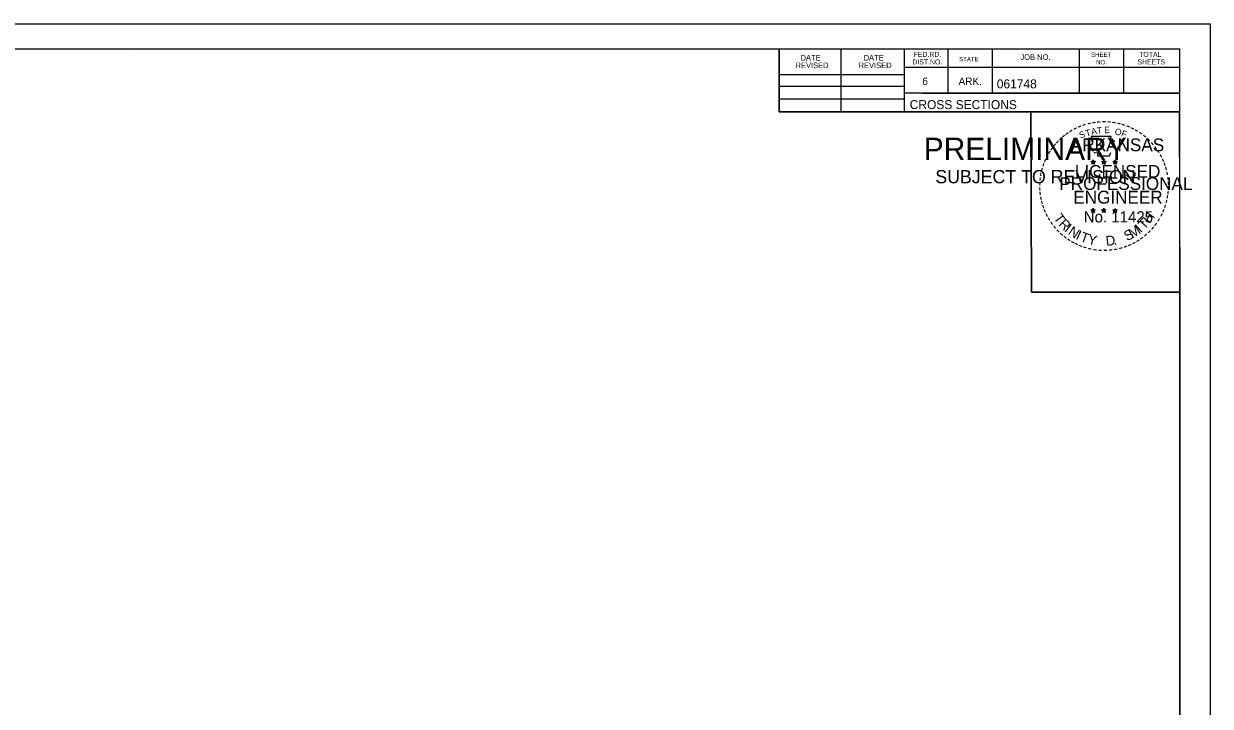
# Model space of a CAD drawing. Extents: x 961436 to 1372525, y 380079 to 2027791.
# Drawn here: x 1370167.9 to 1370353.4, y 380642.4 to 380749.1 of the extents above; entities that cross this region are included whole.
import ezdxf

# ---------------------------------------------------------------- set-up
doc = ezdxf.new("R2010")
doc.units = 0
doc.layers.add('R_No Plot', color=7, linetype='Continuous')

msp = doc.modelspace()

# ---------------------------------------------------------------- linework, layer by layer
at = {"layer": 'R_No Plot'}
for p, q in [((1370020.1, 380749.09), (1370353.44, 380749.09)), ((1370032.5, 380745.19), (1370348.68, 380745.19)), ((1370185.02, 380744.93), (1370185.02, 380744.93)), ((1370185.02, 380744.93), (1370185.02, 380744.93)), ((1370286.04, 380735.31), (1370286.04, 380745.19)), ((1370295.72, 380735.31), (1370295.72, 380745.19)), ((1370305.58, 380745.19), (1370305.58, 380735.31)), ((1370312.42, 380745.19), (1370312.42, 380738.25)), ((1370319.36, 380745.19), (1370319.36, 380738.25)), ((1370332.94, 380745.19), (1370332.94, 380738.25)), ((1370339.88, 380745.19), (1370339.88, 380738.25)), ((1370348.68, 380539.73), (1370348.68, 380745.19)), ((1370348.68, 380742.25), (1370305.58, 380742.25)), ((1370348.68, 380742.27), (1370348.68, 380742.27)), ((1370286.04, 380741.17), (1370305.58, 380741.17)), ((1370286.04, 380739.31), (1370305.58, 380739.31)), ((1370348.68, 380738.25), (1370305.58, 380738.25)), ((1370308.54, 380738.25), (1370348.68, 380738.25)), ((1370286.04, 380737.37), (1370305.58, 380737.37)), ((1370348.68, 380735.31), (1370286.04, 380735.31)), ((1370334.77, 380727.57), (1370335.12, 380727.46)), ((1370334.77, 380727.57), (1370335.02, 380727.53)), ((1370334.77, 380727.57), (1370335.01, 380727.45)), ((1370334.9, 380727.16), (1370335.12, 380727.46)), ((1370334.9, 380727.16), (1370335.03, 380727.41)), ((1370334.9, 380727.16), (1370335.12, 380727.38)), ((1370335.12, 380727.82), (1370335.08, 380727.57)), ((1370335.12, 380727.46), (1370335.12, 380727.82)), ((1370335.12, 380727.82), (1370335.17, 380727.57)), ((1370335.47, 380727.57), (1370335.12, 380727.46)), ((1370335.33, 380727.16), (1370335.12, 380727.46)), ((1370335.33, 380727.16), (1370335.12, 380727.38)), ((1370335.47, 380727.57), (1370335.18, 380727.52)), ((1370335.33, 380727.16), (1370335.19, 380727.45)), ((1370335.47, 380727.57), (1370335.26, 380727.47)), ((1370336.44, 380727.57), (1370336.79, 380727.46)), ((1370336.44, 380727.57), (1370336.69, 380727.53)), ((1370336.44, 380727.57), (1370336.68, 380727.45)), ((1370336.57, 380727.16), (1370336.79, 380727.46)), ((1370336.57, 380727.16), (1370336.7, 380727.41)), ((1370336.57, 380727.16), (1370336.79, 380727.38)), ((1370336.79, 380727.82), (1370336.75, 380727.57)), ((1370336.79, 380727.46), (1370336.79, 380727.82)), ((1370336.79, 380727.82), (1370336.84, 380727.57)), ((1370337.14, 380727.57), (1370336.79, 380727.46)), ((1370337, 380727.16), (1370336.79, 380727.46)), ((1370337, 380727.16), (1370336.79, 380727.38)), ((1370337.14, 380727.57), (1370336.85, 380727.52)), ((1370337, 380727.16), (1370336.86, 380727.45)), ((1370337.14, 380727.57), (1370336.93, 380727.47)), ((1370338.2, 380727.56), (1370338.55, 380727.45)), ((1370338.2, 380727.56), (1370338.46, 380727.51)), ((1370338.2, 380727.56), (1370338.44, 380727.44)), ((1370338.34, 380727.15), (1370338.55, 380727.45)), ((1370338.34, 380727.15), (1370338.46, 380727.39)), ((1370338.34, 380727.15), (1370338.55, 380727.37)), ((1370338.55, 380727.81), (1370338.51, 380727.56)), ((1370338.55, 380727.45), (1370338.55, 380727.81)), ((1370338.55, 380727.81), (1370338.6, 380727.56)), ((1370338.9, 380727.56), (1370338.55, 380727.45)), ((1370338.77, 380727.15), (1370338.55, 380727.45)), ((1370338.77, 380727.15), (1370338.55, 380727.36)), ((1370338.9, 380727.56), (1370338.61, 380727.51)), ((1370338.77, 380727.15), (1370338.63, 380727.44)), ((1370338.9, 380727.56), (1370338.7, 380727.46)), ((1370334.77, 380720), (1370335.11, 380719.89)), ((1370334.77, 380720), (1370335.02, 380719.95)), ((1370334.77, 380720), (1370335, 380719.88)), ((1370334.9, 380719.59), (1370335.11, 380719.89)), ((1370334.9, 380719.59), (1370335.02, 380719.83)), ((1370334.9, 380719.59), (1370335.11, 380719.81)), ((1370335.11, 380720.25), (1370335.07, 380720)), ((1370335.11, 380719.89), (1370335.11, 380720.25)), ((1370335.11, 380720.25), (1370335.16, 380720)), ((1370335.46, 380720), (1370335.11, 380719.89)), ((1370335.33, 380719.59), (1370335.11, 380719.89)), ((1370335.33, 380719.59), (1370335.11, 380719.8)), ((1370335.46, 380720), (1370335.18, 380719.95)), ((1370335.33, 380719.59), (1370335.19, 380719.88)), ((1370335.46, 380720), (1370335.26, 380719.9)), ((1370336.43, 380720), (1370336.78, 380719.89)), ((1370336.43, 380720), (1370336.69, 380719.95)), ((1370336.43, 380720), (1370336.67, 380719.88)), ((1370336.57, 380719.59), (1370336.78, 380719.89)), ((1370336.57, 380719.59), (1370336.69, 380719.83)), ((1370336.57, 380719.59), (1370336.78, 380719.81)), ((1370336.78, 380720.25), (1370336.74, 380720)), ((1370336.78, 380719.89), (1370336.78, 380720.25)), ((1370336.78, 380720.25), (1370336.83, 380720)), ((1370337.13, 380720), (1370336.78, 380719.89)), ((1370337, 380719.59), (1370336.78, 380719.89)), ((1370337, 380719.59), (1370336.78, 380719.8)), ((1370337.13, 380720), (1370336.84, 380719.95)), ((1370337, 380719.59), (1370336.86, 380719.88)), ((1370337.13, 380720), (1370336.93, 380719.9)), ((1370338.2, 380719.99), (1370338.55, 380719.88)), ((1370338.2, 380719.99), (1370338.45, 380719.94)), ((1370338.2, 380719.99), (1370338.44, 380719.87)), ((1370338.33, 380719.58), (1370338.55, 380719.88)), ((1370338.33, 380719.58), (1370338.46, 380719.82)), ((1370338.33, 380719.58), (1370338.55, 380719.8)), ((1370338.55, 380720.24), (1370338.51, 380719.99)), ((1370338.55, 380719.88), (1370338.55, 380720.24)), ((1370338.55, 380720.24), (1370338.6, 380719.99)), ((1370338.9, 380719.99), (1370338.55, 380719.88)), ((1370338.76, 380719.58), (1370338.55, 380719.88)), ((1370338.76, 380719.58), (1370338.55, 380719.79)), ((1370338.9, 380719.99), (1370338.61, 380719.94)), ((1370338.76, 380719.58), (1370338.63, 380719.87)), ((1370338.9, 380719.99), (1370338.69, 380719.89)), ((1370324.72, 380712.86), (1370324.72, 380712.86))]:
    msp.add_line(p, q, dxfattribs=at)
for points in [[(1370020.1, 380749.09), (1370353.44, 380749.09), (1370353.44, 380535.75), (1370020.1, 380535.75)], [(1370266.42, 380745.19), (1370286.04, 380745.19), (1370286.04, 380735.31), (1370302.16, 380735.31), (1370325.36, 380735.31), (1370325.48, 380707.16), (1370348.68, 380707.16), (1370348.68, 380539.73), (1370032.5, 380539.73), (1370032.5, 380745.19)], [(1370325.36, 380735.31), (1370348.56, 380735.31), (1370348.68, 380707.16), (1370325.48, 380707.16)]]:
    msp.add_lwpolyline(points, close=True, dxfattribs=at)
for points in [[(1370334.81, 380731.45), (1370335.08, 380730.62)], [(1370338.32, 380730.53), (1370338.46, 380730.81), (1370337.78, 380730.79), (1370337.93, 380731.45), (1370334.81, 380731.45)], [(1370335.3, 380729.03), (1370335.3, 380728.94), (1370335.87, 380728.92), (1370335.81, 380728.45), (1370337.68, 380728.45), (1370337.88, 380728.98)], [(1370335.12, 380727.82), (1370335.33, 380727.16), (1370334.77, 380727.57), (1370335.47, 380727.57), (1370334.9, 380727.16), (1370335.12, 380727.82)], [(1370336.79, 380727.82), (1370337, 380727.16), (1370336.44, 380727.57), (1370337.14, 380727.57), (1370336.57, 380727.16), (1370336.79, 380727.82)], [(1370338.55, 380727.81), (1370338.77, 380727.15), (1370338.2, 380727.56), (1370338.9, 380727.56), (1370338.34, 380727.15), (1370338.55, 380727.81)], [(1370335.11, 380720.25), (1370335.33, 380719.59), (1370334.77, 380720), (1370335.46, 380720), (1370334.9, 380719.59), (1370335.11, 380720.25)], [(1370336.78, 380720.25), (1370337, 380719.59), (1370336.43, 380720), (1370337.13, 380720), (1370336.57, 380719.59), (1370336.78, 380720.25)], [(1370338.55, 380720.24), (1370338.76, 380719.58), (1370338.2, 380719.99), (1370338.9, 380719.99), (1370338.33, 380719.58), (1370338.55, 380720.24)]]:
    msp.add_lwpolyline(points, dxfattribs=at)
for centre, radius in [((1370335.12, 380727.46), 0.172), ((1370335.12, 380727.46), 0.145), ((1370335.12, 380727.46), 0.116), ((1370335.12, 380727.46), 0.0991), ((1370335.12, 380727.46), 0.0747), ((1370335.12, 380727.46), 0.0495), ((1370335.12, 380727.46), 0.0296), ((1370336.79, 380727.46), 0.172), ((1370336.79, 380727.46), 0.145), ((1370336.79, 380727.46), 0.116), ((1370336.79, 380727.46), 0.0991), ((1370336.79, 380727.46), 0.0747), ((1370336.79, 380727.46), 0.0495), ((1370336.79, 380727.46), 0.0296), ((1370338.55, 380727.45), 0.172), ((1370338.55, 380727.45), 0.145), ((1370338.55, 380727.45), 0.116), ((1370338.55, 380727.45), 0.0991), ((1370338.55, 380727.45), 0.0747), ((1370338.55, 380727.45), 0.0495), ((1370338.55, 380727.45), 0.0296), ((1370335.11, 380719.89), 0.172), ((1370335.11, 380719.89), 0.145), ((1370335.11, 380719.89), 0.116), ((1370335.11, 380719.89), 0.0991), ((1370335.11, 380719.89), 0.0747), ((1370335.11, 380719.89), 0.0495), ((1370335.11, 380719.89), 0.0296), ((1370336.78, 380719.89), 0.172), ((1370336.78, 380719.89), 0.145), ((1370336.78, 380719.89), 0.116), ((1370336.78, 380719.89), 0.0991), ((1370336.78, 380719.89), 0.0747), ((1370336.78, 380719.89), 0.0495), ((1370336.78, 380719.89), 0.0296), ((1370338.55, 380719.88), 0.172), ((1370338.55, 380719.88), 0.145), ((1370338.55, 380719.88), 0.116), ((1370338.55, 380719.88), 0.0991), ((1370338.55, 380719.88), 0.0747), ((1370338.55, 380719.88), 0.0495), ((1370338.55, 380719.88), 0.0296)]:
    msp.add_circle(centre, radius, dxfattribs=at)

# ---------------------------------------------------------------- texts
for s, height, rotation, p in [('DATE', 0.879, 360, (1370289.38, 380743.33)), ('DATE', 0.879, 360, (1370299.24, 380743.33)), ('FED.RD.', 0.782, 360, (1370307.06, 380743.91)), ('STATE', 0.684, 360, (1370314.18, 380743.23)), ('JOB NO.', 0.879, 360, (1370323.76, 380743.43)), ('SHEET', 0.684, 360, (1370334.8, 380743.91)), ('TOTAL', 0.782, 360, (1370342.32, 380743.91)), ('REVISED', 0.879, 360, (1370288.6, 380742.15)), ('REVISED', 0.879, 360, (1370298.46, 380742.15)), ('DIST.NO.', 0.782, 360, (1370306.86, 380742.73)), ('NO.', 0.684, 360, (1370335.58, 380742.73)), ('SHEETS', 0.782, 360, (1370342.04, 380742.73)), ('6', 1.17, 360, (1370308.42, 380739.51)), ('ARK.', 1.172, 360, (1370314.08, 380739.51)), ('061748', 1.4, 360, (1370320.06, 380738.99)), ('CROSS SECTIONS', 1.4, 360, (1370306.45, 380735.75)), ('-', 1.6, 34.0636, (1370331.69, 380731.62)), ('-', 1.6, 28.7918, (1370332.29, 380731.99)), ('-', 1.6, 24.3072, (1370332.92, 380732.31)), ('-', 1.6, 19.1761, (1370333.56, 380732.58)), ('T', 1, 16.4036, (1370334.08, 380731.46)), ('-', 1.6, 13.6301, (1370334.31, 380732.82)), ('A', 1, 11.2132, (1370334.91, 380731.71)), ('-', 1.6, 10.2193, (1370334.99, 380732.98)), ('T', 1, 6.0228, (1370335.75, 380731.87)), ('-', 1.6, 5.8968, (1370335.72, 380733.09)), ('-', 1.6, 0.1862, (1370336.49, 380733.16)), ('E', 1, 0.8323, (1370336.86, 380731.98)), ('-', 1.6, 357.743, (1370337.21, 380733.15)), ('-', 1.6, 352.1617, (1370337.95, 380733.09)), ('O', 1, 350.4515, (1370338.46, 380731.77)), ('-', 1.6, 347.2049, (1370338.67, 380732.98)), ('-', 1.6, 342.3362, (1370339.31, 380732.82)), ('-', 1.6, 337.8551, (1370340.04, 380732.6)), ('-', 1.6, 334.1211, (1370340.67, 380732.33)), ('-', 1.6, 329.6409, (1370341.25, 380732.05)), ('PRELIMINARY', 3.5, 360, (1370308.64, 380727.78)), ('-', 1.6, 48.423, (1370329.76, 380729.95)), ('-', 1.6, 42.9622, (1370330.21, 380730.43)), ('-', 1.6, 38.9507, (1370330.64, 380730.85)), ('-', 1.6, 36.2317, (1370331.12, 380731.22)), ('ARKANSAS', 2, 360, (1370331.66, 380729.16)), ('S', 1, 21.594, (1370333.17, 380731.13)), ('F', 1, 340.0707, (1370339.42, 380731.55)), ('-', 1.6, 325.8627, (1370341.9, 380731.68)), ('-', 1.6, 320.5297, (1370342.51, 380731.26)), ('-', 1.6, 315.5786, (1370343.11, 380730.77)), ('DWB', 0.01, 360, (1370309.38, 380729.63)), ('-', 1.6, 58.0706, (1370328.62, 380728.37)), ('-', 1.6, 54.2325, (1370328.94, 380728.9)), ('-', 1.6, 50.6142, (1370329.36, 380729.47)), ('-', 1.6, 309.8797, (1370343.67, 380730.22)), ('-', 1.6, 306.6522, (1370344.2, 380729.62)), ('-', 1.4, 303.6753, (1370344.69, 380729.05)), ('-', 1.6, 72.3945, (1370327.83, 380726.52)), ('-', 1.6, 67.7743, (1370328.05, 380727.15)), ('-', 1.6, 62.8713, (1370328.31, 380727.76)), ('LICENSED', 2, 360, (1370332.26, 380725.01)), ('DWB', 0.01, 360, (1370335.11, 380727.45)), ('DWB', 0.01, 360, (1370336.78, 380727.45)), ('DWB', 0.01, 360, (1370338.54, 380727.44)), ('-', 1.6, 299.6684, (1370345, 380728.44)), ('-', 1.6, 294.6628, (1370345.33, 380727.83)), ('-', 1.6, 290.5728, (1370345.59, 380727.25)), ('SUBJECT TO REVISION', 2.0751, 360, (1370310.45, 380724.15)), ('-', 1.6, 81.2013, (1370327.5, 380725.09)), ('-', 1.6, 75.461, (1370327.63, 380725.8)), ('PROFESSIONAL', 2, 360, (1370329.84, 380723.11)), ('-', 1.6, 285.1233, (1370345.82, 380726.67)), ('-', 1.6, 280.5493, (1370346.02, 380725.93)), ('-', 1.6, 276.5962, (1370346.18, 380725.16)), ('-', 1.6, 94.1959, (1370327.43, 380722.97)), ('-', 1.6, 89.0622, (1370327.4, 380723.7)), ('-', 1.6, 85.1863, (1370327.42, 380724.4)), ('-', 1.6, 274.3301, (1370346.24, 380724.44)), ('-', 1.6, 269.9407, (1370346.28, 380723.81)), ('-', 1.6, 98.9479, (1370327.5, 380722.31)), ('-', 1.6, 101.7149, (1370327.64, 380721.57)), ('-', 1.6, 105.4578, (1370327.8, 380720.98)), ('ENGINEER', 2, 360, (1370332.02, 380720.98)), ('-', 1.6, 255.7626, (1370346.08, 380721.81)), ('-', 1.6, 260.9953, (1370346.19, 380722.49)), ('-', 1.6, 263.5172, (1370346.26, 380723.14)), ('-', 1.6, 109.0874, (1370328.02, 380720.35)), ('-', 1.6, 114.0643, (1370328.27, 380719.75)), ('T', 1.54, 306.0406, (1370328.87, 380718.72)), ('No. 11425', 1.757, 360, (1370333.65, 380718.03)), ('DWB', 0.01, 360, (1370335.1, 380719.88)), ('DWB', 0.01, 360, (1370336.77, 380719.88)), ('DWB', 0.01, 360, (1370338.54, 380719.87)), ('H', 1.54, 54.6088, (1370343.99, 380717.76)), ('-', 1.6, 247.8887, (1370345.67, 380720.42)), ('-', 1.6, 252.8681, (1370345.89, 380721.09)), ('-', 1.6, 115.7289, (1370328.58, 380719.13)), ('-', 1.6, 120.4471, (1370328.93, 380718.55)), ('-', 1.6, 125.8934, (1370329.34, 380717.99)), ('R', 1.54, 314.005, (1370329.64, 380717.68)), ('I', 1.54, 321.9694, (1370330.54, 380716.74)), ('I', 1.54, 42.1136, (1370342.54, 380716.34)), ('T', 1.54, 46.6444, (1370343.11, 380716.82)), ('-', 1.6, 233.8452, (1370344.61, 380718.39)), ('-', 1.6, 239.0712, (1370345.02, 380719.04)), ('-', 1.6, 244.6197, (1370345.41, 380719.79)), ('-', 1.6, 130.7181, (1370329.8, 380717.43)), ('-', 1.6, 134.2238, (1370330.31, 380716.89)), ('-', 1.6, 138.9338, (1370330.84, 380716.42)), ('-', 1.6, 144.6463, (1370331.4, 380716.02)), ('N', 1.54, 326.5002, (1370331.1, 380716.27)), ('I', 1.54, 335.3603, (1370332.31, 380715.49)), ('T', 1.54, 339.8912, (1370332.97, 380715.16)), ('Y', 1.54, 347.8556, (1370334.19, 380714.71)), ('D', 1.54, 6.3969, (1370337.18, 380714.36)), ('S', 1.54, 26.9312, (1370340.42, 380715.09)), ('M', 1.54, 32.6563, (1370341.26, 380715.49)), ('-', 1.6, 221.0851, (1370343.18, 380716.75)), ('-', 1.6, 225.7653, (1370343.7, 380717.26)), ('-', 1.6, 231.2538, (1370344.18, 380717.82)), ('-', 1.6, 148.0898, (1370331.96, 380715.65)), ('-', 1.6, 151.5704, (1370332.54, 380715.32)), ('-', 1.6, 154.6002, (1370333.06, 380715.08)), ('-', 1.6, 158.5612, (1370333.68, 380714.82)), ('-', 1.6, 162.7983, (1370334.37, 380714.61)), ('-', 1.6, 167.5555, (1370335.08, 380714.44)), ('-', 1.6, 191.2858, (1370338.89, 380714.51)), ('.', 1.54, 13.7642, (1370338.37, 380714.48)), ('-', 1.6, 195.4743, (1370339.62, 380714.71)), ('-', 1.6, 200.7184, (1370340.3, 380714.95)), ('-', 1.6, 204.2516, (1370340.92, 380715.22)), ('-', 1.6, 207.3568, (1370341.54, 380715.54)), ('-', 1.6, 212.2491, (1370342.1, 380715.89)), ('-', 1.6, 215.7363, (1370342.63, 380716.27)), ('-', 1.6, 173.1155, (1370335.86, 380714.33)), ('-', 1.6, 176.5183, (1370336.6, 380714.28)), ('-', 1.6, 181.5918, (1370337.35, 380714.3)), ('-', 1.6, 185.8167, (1370338.16, 380714.38))]:
    msp.add_text(s, height=height, rotation=rotation, dxfattribs=at).set_placement(p)

doc.saveas('drawing.dxf')
